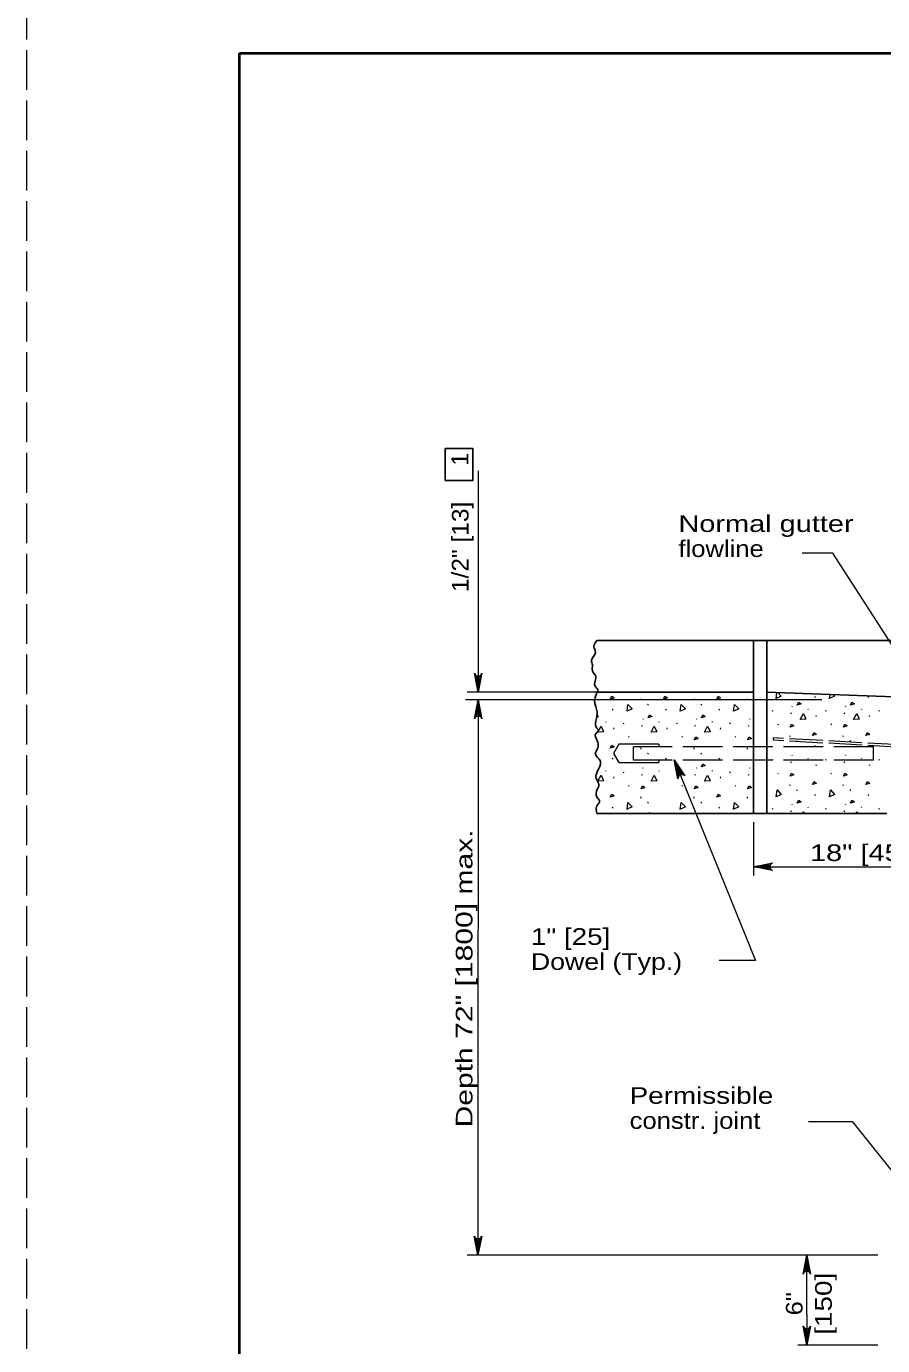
# Model space of a CAD drawing. Extents: x 1083.1 to 1117.1, y 719.4 to 763.4.
# Drawn here: x 1083.13 to 1091.16, y 728.74 to 741.1 of the extents above; entities that cross this region are included whole.
import ezdxf
from ezdxf.enums import TextEntityAlignment as Align

# ---------------------------------------------------------------- set-up
doc = ezdxf.new("R2010")
doc.units = 0
doc.header["$LTSCALE"] = 0.062
doc.linetypes.add('LONG_DASHED', pattern=[7.5, 6, -1.5])
doc.layers.add('1', color=7, linetype='Continuous', lineweight=13)

msp = doc.modelspace()

# ---------------------------------------------------------------- linework, layer by layer
at = {"layer": '1', "lineweight": 25}
for p, q in [((1085.12642, 740.85408), (1116.62642, 740.85408)), ((1089.9465, 735.34842), (1089.9465, 733.72892)), ((1088.47783, 734.86417), (1089.9465, 734.86417)), ((1090.0715, 734.86417), (1092.04017, 734.79308)), ((1089.9465, 733.72892), (1090.0715, 733.72892))]:
    msp.add_line(p, q, dxfattribs=at)
at = {"layer": '1'}
for p, q in [((1087.36392, 736.94033), (1087.36392, 734.86408)), ((1087.3415, 735.02442), (1087.36392, 734.86408)), ((1087.35258, 735.01892), (1087.36392, 734.86408)), ((1087.38875, 735.02625), (1087.36392, 734.86408)), ((1087.37833, 735.02017), (1087.36392, 734.86408)), ((1087.36392, 735.01733), (1087.36392, 734.86408)), ((1090.5885, 734.79308), (1087.2445, 734.79308)), ((1088.47783, 734.86417), (1087.26208, 734.86417)), ((1087.33917, 734.63075), (1087.36392, 734.79292)), ((1087.34958, 734.63683), (1087.36392, 734.79292)), ((1087.36392, 734.63967), (1087.36392, 734.79292)), ((1087.37525, 734.638), (1087.36392, 734.79292)), ((1087.38642, 734.63258), (1087.36392, 734.79292)), ((1088.88692, 734.80117), (1088.88808, 734.79117)), ((1088.95617, 734.74225), (1088.96058, 734.75225)), ((1089.38683, 734.80117), (1089.388, 734.79117)), ((1089.45608, 734.74225), (1089.4605, 734.75225)), ((1089.88683, 734.80117), (1089.888, 734.79117)), ((1090.15817, 734.80342), (1090.16617, 734.86075)), ((1090.52308, 734.81483), (1090.52758, 734.82483)), ((1090.65817, 734.80342), (1090.66367, 734.84275)), ((1091.023, 734.81483), (1091.0275, 734.82483)), ((1088.62483, 734.69667), (1088.62933, 734.70667)), ((1089.12475, 734.69667), (1089.12933, 734.70667)), ((1089.62475, 734.69667), (1089.62925, 734.70667)), ((1090.12417, 734.68608), (1090.12858, 734.69608)), ((1090.29733, 734.66292), (1090.30175, 734.67292)), ((1090.30567, 734.73608), (1090.31017, 734.72942)), ((1090.45525, 734.70783), (1090.45967, 734.70117)), ((1090.53425, 734.63742), (1090.53867, 734.64742)), ((1090.62417, 734.68608), (1090.62858, 734.69608)), ((1090.79733, 734.66292), (1090.80175, 734.67292)), ((1090.80567, 734.73608), (1090.81017, 734.72942)), ((1090.95517, 734.70783), (1090.95958, 734.70117)), ((1091.03417, 734.63742), (1091.03858, 734.64742)), ((1091.12408, 734.68608), (1091.1285, 734.69608)), ((1088.557, 734.58967), (1088.56142, 734.583)), ((1088.636, 734.51933), (1088.64042, 734.52933)), ((1088.72592, 734.56792), (1088.73033, 734.57792)), ((1088.89908, 734.54475), (1088.9035, 734.55475)), ((1088.90742, 734.61792), (1088.91192, 734.61125)), ((1089.057, 734.58967), (1089.06142, 734.583)), ((1089.136, 734.51933), (1089.14033, 734.52933)), ((1089.22583, 734.56792), (1089.23025, 734.57792)), ((1089.399, 734.54475), (1089.40342, 734.55475)), ((1089.40733, 734.61792), (1089.41183, 734.61125)), ((1089.55692, 734.58967), (1089.56133, 734.583)), ((1089.63592, 734.51933), (1089.64033, 734.52933)), ((1089.72583, 734.56792), (1089.73025, 734.57792)), ((1089.899, 734.54475), (1089.90342, 734.55475)), ((1089.90733, 734.61792), (1089.91183, 734.61125)), ((1090.173, 734.56633), (1090.17742, 734.55967)), ((1090.673, 734.56633), (1090.67742, 734.55967)), ((1088.77475, 734.44825), (1088.77917, 734.44167)), ((1089.27467, 734.44825), (1089.27908, 734.44167)), ((1089.77467, 734.44825), (1089.77908, 734.44167)), ((1090.28517, 734.46), (1090.28633, 734.45)), ((1090.35442, 734.40108), (1090.35883, 734.41108)), ((1090.78517, 734.46), (1090.78633, 734.45)), ((1090.85442, 734.40108), (1090.85883, 734.41108)), ((1088.88692, 734.34183), (1088.88808, 734.33183)), ((1088.95617, 734.28292), (1088.96058, 734.29292)), ((1089.05867, 734.37725), (1089.05867, 734.35383)), ((1089.38683, 734.34183), (1089.388, 734.33183)), ((1089.45608, 734.28292), (1089.4605, 734.29292)), ((1089.88683, 734.34183), (1089.888, 734.33183)), ((1090.30567, 734.27675), (1090.31017, 734.27008)), ((1090.52308, 734.3555), (1090.52758, 734.3655)), ((1090.80567, 734.27675), (1090.81017, 734.27008)), ((1091.023, 734.3555), (1091.0275, 734.3655)), ((1088.62483, 734.23733), (1088.62933, 734.24733)), ((1088.90742, 734.15858), (1088.91192, 734.15192)), ((1089.05867, 734.22883), (1089.05867, 734.20542)), ((1089.12475, 734.23733), (1089.12933, 734.24733)), ((1089.261, 734.08767), (1089.20233, 734.22925)), ((1089.24875, 734.07958), (1089.20233, 734.22925)), ((1089.2415, 734.06992), (1089.20233, 734.22925)), ((1089.27208, 734.0905), (1089.20233, 734.22925)), ((1089.28442, 734.08975), (1089.20233, 734.22925)), ((1089.40733, 734.15858), (1089.41183, 734.15192)), ((1089.62475, 734.23733), (1089.62925, 734.24733)), ((1089.90733, 734.15858), (1089.91183, 734.15192)), ((1090.12417, 734.22675), (1090.12858, 734.23675)), ((1090.29733, 734.20358), (1090.30175, 734.21358)), ((1090.45525, 734.2485), (1090.45967, 734.24183)), ((1090.53425, 734.17808), (1090.53867, 734.18808)), ((1090.62417, 734.22675), (1090.62858, 734.23675)), ((1090.79733, 734.20358), (1090.80175, 734.21358)), ((1090.95517, 734.2485), (1090.95958, 734.24183)), ((1091.03417, 734.17808), (1091.03858, 734.18808)), ((1091.12408, 734.22675), (1091.1285, 734.23675)), ((1088.557, 734.13033), (1088.56142, 734.12367)), ((1088.636, 734.05992), (1088.64042, 734.06992)), ((1088.72592, 734.10867), (1088.73033, 734.11858)), ((1088.89908, 734.08542), (1088.9035, 734.09542)), ((1089.057, 734.13033), (1089.06142, 734.12367)), ((1089.399, 734.08542), (1089.40342, 734.09542)), ((1089.55692, 734.13033), (1089.56133, 734.12367)), ((1089.63592, 734.05992), (1089.64033, 734.06992)), ((1089.72583, 734.10867), (1089.73025, 734.11858)), ((1089.899, 734.08542), (1089.90342, 734.09542)), ((1090.173, 734.107), (1090.17742, 734.10033)), ((1090.673, 734.107), (1090.67742, 734.10033)), ((1088.77475, 733.98892), (1088.77917, 733.98233)), ((1089.27467, 733.98892), (1089.27908, 733.98233)), ((1089.77467, 733.98892), (1089.77908, 733.98233)), ((1090.28517, 734.00058), (1090.28633, 733.99067)), ((1090.35442, 733.94175), (1090.35883, 733.95175)), ((1090.52308, 733.89617), (1090.52758, 733.90617)), ((1090.78517, 734.00058), (1090.78633, 733.99067)), ((1090.85442, 733.94175), (1090.85883, 733.95175)), ((1091.023, 733.89617), (1091.0275, 733.90617)), ((1088.62483, 733.77808), (1088.62933, 733.78808)), ((1088.88692, 733.8825), (1088.88808, 733.8725)), ((1088.95617, 733.82358), (1088.96058, 733.83358)), ((1089.38683, 733.8825), (1089.388, 733.8725)), ((1089.45608, 733.82358), (1089.4605, 733.83358)), ((1089.62475, 733.77808), (1089.62925, 733.78808)), ((1089.88683, 733.8825), (1089.888, 733.8725)), ((1090.12417, 733.76742), (1090.12858, 733.77742)), ((1090.30567, 733.81742), (1090.31017, 733.81075)), ((1090.45525, 733.78917), (1090.45967, 733.7825)), ((1090.62417, 733.76742), (1090.62858, 733.77742)), ((1090.80567, 733.81742), (1090.81017, 733.81075)), ((1090.95517, 733.78917), (1090.95958, 733.7825)), ((1091.12408, 733.76742), (1091.1285, 733.77742)), ((1088.47775, 733.73017), (1088.47942, 733.72892)), ((1089.9465, 733.64558), (1089.9465, 733.14567)), ((1090.29733, 733.74425), (1090.30175, 733.75425)), ((1090.79733, 733.74425), (1090.80175, 733.75425)), ((1090.10683, 733.25142), (1089.9465, 733.229)), ((1090.10142, 733.24033), (1089.9465, 733.229)), ((1089.9465, 733.229), (1091.15692, 733.229)), ((1090.09975, 733.229), (1089.9465, 733.229)), ((1090.10258, 733.21458), (1089.9465, 733.229)), ((1090.10867, 733.20417), (1089.9465, 733.229)), ((1091.15692, 733.229), (1092.1965, 733.229)), ((1087.33942, 729.74917), (1087.36183, 729.58892)), ((1087.3505, 729.74375), (1087.36183, 729.58892)), ((1087.38658, 729.75108), (1087.36183, 729.58892)), ((1087.37625, 729.74492), (1087.36183, 729.58892)), ((1087.36183, 729.74208), (1087.36183, 729.58892)), ((1091.11308, 729.58892), (1087.26208, 729.58892)), ((1090.42167, 729.42667), (1090.4465, 729.58892)), ((1090.43208, 729.43283), (1090.4465, 729.58892)), ((1090.4465, 729.03167), (1090.4465, 729.58892)), ((1090.4465, 729.43567), (1090.4465, 729.58892)), ((1090.45783, 729.434), (1090.4465, 729.58892)), ((1090.46892, 729.42858), (1090.4465, 729.58892)), ((1090.4465, 729.03167), (1090.4465, 728.74517)), ((1090.42408, 728.90558), (1090.4465, 728.74525)), ((1090.43517, 728.90017), (1090.4465, 728.74525)), ((1090.47125, 728.90742), (1090.4465, 728.74525)), ((1090.46092, 728.90133), (1090.4465, 728.74525)), ((1090.4465, 728.8985), (1090.4465, 728.74525)), ((1091.11308, 728.74525), (1090.36317, 728.74525))]:
    msp.add_line(p, q, dxfattribs=at)
at = {"layer": '1', "linetype": 'LONG_DASHED'}
for p, q in [((1090.13317, 734.414), (1090.1345, 734.43683)), ((1090.2295, 734.40867), (1090.13317, 734.414)), ((1090.22808, 734.43158), (1090.1345, 734.43683)), ((1090.59583, 734.41117), (1090.28375, 734.4285)), ((1090.59725, 734.38825), (1090.28525, 734.40558)), ((1090.9635, 734.39075), (1090.65158, 734.40808)), ((1090.96492, 734.36783), (1090.65308, 734.38517)), ((1091.33125, 734.37033), (1091.01917, 734.38767)), ((1088.82158, 734.22883), (1088.82158, 734.35383)), ((1091.33275, 734.34742), (1091.02067, 734.36475)), ((1091.07142, 734.22883), (1088.82158, 734.22883))]:
    msp.add_line(p, q, dxfattribs=at)
msp.add_lwpolyline([(1083.12642, 719.35408), (1117.12642, 719.35408), (1117.12642, 741.35408), (1083.12642, 741.35408)], close=True, dxfattribs=at)
at = {"layer": '1', "lineweight": 25}
for points in [[(1116.62642, 719.85408), (1085.12642, 719.85408), (1085.12642, 740.85408)], [(1088.47783, 735.34842), (1089.9465, 735.34842), (1090.0715, 735.34842)], [(1091.19642, 733.72892), (1090.0715, 733.72892), (1090.0715, 735.34842)], [(1090.0715, 735.34842), (1091.29683, 735.34842), (1093.0845, 735.34842), (1094.87617, 735.34842), (1097.69617, 735.34842)], [(1089.9465, 733.72892), (1088.99875, 733.72892), (1088.47783, 733.72892)], [(1088.96883, 733.72892), (1088.97167, 733.73475), (1088.97942, 733.72892)]]:
    msp.add_lwpolyline(points, dxfattribs=at)
at = {"layer": '1', "lineweight": 40}
msp.add_lwpolyline([(1085.12642, 740.85408), (1116.62642, 740.85408), (1116.62642, 719.85408), (1085.12642, 719.85408)], close=True, dxfattribs=at)
msp.add_lwpolyline([(1085.12642, 740.85408), (1116.62642, 740.85408), (1116.62642, 719.85408), (1085.12642, 719.85408)], close=True, dxfattribs=at)
at = {"layer": '1', "lineweight": 25}
msp.add_lwpolyline([(1087.05342, 736.84933), (1087.31508, 736.84933), (1087.31508, 737.14817), (1087.05342, 737.14817)], close=True, dxfattribs=at)
at = {"layer": '1'}
for points in [[(1091.53008, 734.86417), (1090.6915, 736.16683), (1090.40142, 736.16683)], [(1087.39933, 735.04117), (1087.36392, 734.86408), (1087.3285, 735.04117)], [(1087.3285, 734.61583), (1087.36392, 734.79292), (1087.39933, 734.61583)], [(1087.36392, 734.79292), (1087.36217, 730.49425), (1087.36183, 729.58892)], [(1090.17317, 734.8605), (1090.20675, 734.82575), (1090.15917, 734.80375)], [(1090.69125, 734.84175), (1090.70675, 734.82575), (1090.65917, 734.80375)], [(1088.47658, 734.64975), (1088.49392, 734.63675), (1088.47475, 734.63075)], [(1088.75992, 734.68525), (1088.76875, 734.74867), (1088.8085, 734.70758), (1088.76092, 734.68558)], [(1089.25983, 734.68525), (1089.26867, 734.74867), (1089.30842, 734.70758), (1089.26083, 734.68558)], [(1089.75983, 734.68525), (1089.76867, 734.74867), (1089.80842, 734.70758), (1089.76083, 734.68558)], [(1090.38433, 734.60742), (1090.41433, 734.664), (1090.43767, 734.61192), (1090.3855, 734.60742)], [(1090.88433, 734.60742), (1090.91425, 734.664), (1090.93767, 734.61192), (1090.8855, 734.60742)], [(1088.48608, 734.48933), (1088.51608, 734.54592), (1088.53942, 734.49383), (1088.48725, 734.48933)], [(1088.98608, 734.48933), (1089.01608, 734.54592), (1089.03942, 734.49383), (1088.98725, 734.48933)], [(1089.486, 734.48933), (1089.516, 734.54592), (1089.53933, 734.49383), (1089.48717, 734.48933)], [(1089.05867, 734.37725), (1088.68367, 734.37725), (1088.63408, 734.29133), (1088.68367, 734.20542), (1089.05867, 734.20542)], [(1089.23742, 734.05208), (1089.20233, 734.22925), (1089.30283, 734.07925)], [(1089.20233, 734.22925), (1089.96633, 732.34867), (1089.6245, 732.34867)], [(1088.48608, 734.02992), (1088.51608, 734.08658), (1088.53942, 734.03442), (1088.48725, 734.02992)], [(1088.98608, 734.02992), (1089.01608, 734.08658), (1089.03942, 734.03442), (1088.98725, 734.02992)], [(1089.486, 734.02992), (1089.516, 734.08658), (1089.53933, 734.03442), (1089.48717, 734.02992)], [(1090.15817, 733.88475), (1090.167, 733.94817), (1090.20675, 733.90708), (1090.15917, 733.88508)], [(1090.65817, 733.88475), (1090.667, 733.94817), (1090.70675, 733.90708), (1090.65917, 733.88508)], [(1088.75992, 733.76658), (1088.76875, 733.83), (1088.8085, 733.78892), (1088.76092, 733.76692)], [(1089.25983, 733.76658), (1089.26867, 733.83), (1089.30842, 733.78892), (1089.26083, 733.76692)], [(1089.75983, 733.76658), (1089.76867, 733.83), (1089.80842, 733.78892), (1089.76083, 733.76692)], [(1089.46875, 733.72892), (1089.47158, 733.73475), (1089.47933, 733.72892)], [(1090.40558, 733.72892), (1090.41433, 733.74542), (1090.42175, 733.72892)], [(1090.90558, 733.72892), (1090.91425, 733.74542), (1090.92175, 733.72892)], [(1090.12358, 733.19358), (1089.9465, 733.229), (1090.12358, 733.26442)], [(1091.81125, 729.6685), (1090.87792, 730.83792), (1090.46358, 730.83792)], [(1087.39725, 729.76592), (1087.36183, 729.58892), (1087.32642, 729.76592)], [(1090.41108, 729.41183), (1090.4465, 729.58892), (1090.48192, 729.41183)], [(1090.48192, 728.92233), (1090.4465, 728.74525), (1090.41108, 728.92233)]]:
    msp.add_lwpolyline(points, dxfattribs=at)
for points in [[(1088.60292, 734.79942), (1088.61625, 734.82717), (1088.63842, 734.8105)], [(1089.10292, 734.79942), (1089.11625, 734.82717), (1089.13833, 734.8105)], [(1089.60283, 734.79942), (1089.61617, 734.82717), (1089.63833, 734.8105)], [(1090.35658, 734.74383), (1090.36992, 734.77158), (1090.39217, 734.75492)], [(1090.85658, 734.74383), (1090.86992, 734.77158), (1090.89217, 734.75492)], [(1088.95833, 734.62567), (1088.97167, 734.65342), (1088.99392, 734.63675)], [(1089.45825, 734.62567), (1089.47158, 734.65342), (1089.49383, 734.63675)], [(1090.2895, 734.5375), (1090.30283, 734.56525), (1090.32508, 734.54858)], [(1090.7895, 734.5375), (1090.80283, 734.56525), (1090.82508, 734.54858)], [(1089.39117, 734.41942), (1089.4045, 734.44717), (1089.42675, 734.4305)], [(1089.89117, 734.41942), (1089.9045, 734.44717), (1089.92675, 734.4305)], [(1090.50117, 734.45825), (1090.5145, 734.486), (1090.53667, 734.46933)], [(1091.00108, 734.45825), (1091.01442, 734.486), (1091.03658, 734.46933)], [(1088.60292, 734.34008), (1088.61625, 734.36783), (1088.63842, 734.35117)], [(1089.45825, 734.16633), (1089.47158, 734.19408), (1089.49383, 734.17742)], [(1090.2895, 734.07817), (1090.30283, 734.10592), (1090.32508, 734.08925)], [(1090.50117, 733.99883), (1090.5145, 734.02658), (1090.53667, 734.00992)], [(1090.7895, 734.07817), (1090.80283, 734.10592), (1090.82508, 734.08925)], [(1091.00108, 733.99883), (1091.01442, 734.02658), (1091.03658, 734.00992)], [(1088.60292, 733.88075), (1088.61625, 733.9085), (1088.63842, 733.89183)], [(1088.89125, 733.96008), (1088.90458, 733.98783), (1088.92683, 733.97117)], [(1089.39117, 733.96008), (1089.4045, 733.98783), (1089.42675, 733.97117)], [(1089.60283, 733.88075), (1089.61617, 733.9085), (1089.63833, 733.89183)], [(1089.89117, 733.96008), (1089.9045, 733.98783), (1089.92675, 733.97117)], [(1090.35658, 733.82517), (1090.36992, 733.85292), (1090.39217, 733.83625)], [(1090.85658, 733.82517), (1090.86992, 733.85292), (1090.89217, 733.83625)]]:
    msp.add_lwpolyline(points, close=True, dxfattribs=at)
at = {"layer": '1', "linetype": 'LONG_DASHED'}
msp.add_lwpolyline([(1091.07142, 734.22883), (1091.07142, 734.35383), (1088.82158, 734.35383)], dxfattribs=at)
at = {"layer": '1'}
for centre, start, end in [((1087.36391, 735.05545), 202.08782, 337.91395), ((1087.36399, 734.60154), 22.08782, 157.91395), ((1089.27563, 734.05247), 44.58395, 180.41008), ((1090.13788, 733.22903), 112.08782, 247.91395), ((1087.36177, 729.78026), 202.08782, 337.91395), ((1090.44652, 729.39751), 22.08782, 157.91395), ((1090.44644, 728.93663), 202.08782, 337.91395)]:
    msp.add_arc(centre, 0.03822, start, end, dxfattribs=at)
at = {"layer": '1', "lineweight": 25}
for points in [[(1088.47783, 734.86417), (1088.48633, 734.88942), (1088.46683, 734.91092), (1088.457, 734.95192), (1088.46875, 735.00667), (1088.43558, 735.06525), (1088.43558, 735.11992), (1088.42775, 735.16292), (1088.46292, 735.23525), (1088.44925, 735.29383), (1088.47783, 735.34842)], [(1088.47783, 734.86417), (1088.46683, 734.83217), (1088.457, 734.76575), (1088.46683, 734.73058), (1088.4785, 734.68167), (1088.46875, 734.59375), (1088.47658, 734.52742), (1088.49408, 734.50783), (1088.48242, 734.49025), (1088.46092, 734.46292), (1088.48042, 734.41208), (1088.48633, 734.34367), (1088.46292, 734.28308), (1088.50775, 734.2245), (1088.47067, 734.09158), (1088.47267, 734.04858), (1088.49608, 733.99975), (1088.47458, 733.93725), (1088.48633, 733.86883), (1088.48825, 733.86692), (1088.50192, 733.8415), (1088.48825, 733.81608), (1088.47267, 733.79067), (1088.47783, 733.72892)]]:
    msp.add_spline(points, degree=3, dxfattribs=at)

# ---------------------------------------------------------------- texts
at = {"layer": '1'}
msp.add_text('1', height=0.16, rotation=90, dxfattribs=at).set_placement((1087.27258, 736.98808))
for s, width, p in [('1/2" [13]', 1.1, (1087.2735, 736.22621)), ('[150]', 1.25, (1090.68042, 729.13317)), ('6"', 1.15, (1090.40633, 729.13317))]:
    msp.add_text(s, height=0.156, rotation=90, dxfattribs=dict(at, width=width)).set_placement(p, align=Align.CENTER)
for s, width, p in [('Normal gutter', 1.3, (1089.24233, 736.36608)), ('flowline', 1.15, (1089.24233, 736.13142)), ('1" [25]', 1.25, (1087.85842, 732.49642)), ('Dowel (Typ.)', 1.2, (1087.85842, 732.26175)), ('Permissible', 1.25, (1088.78475, 731.00667)), ('constr. joint', 1.15, (1088.78475, 730.772))]:
    msp.add_text(s, height=0.156, dxfattribs=dict(at, width=width)).set_placement(p)
at = {"layer": '1', "width": 1.35}
msp.add_text('Depth 72" [1800] max.', height=0.156, rotation=90, dxfattribs=at).set_placement((1087.31025, 730.7855))
at = {"layer": '1', "width": 1.3}
msp.add_text('18" [450]', height=0.156, dxfattribs=at).set_placement((1091.01463, 733.28192), align=Align.CENTER)

doc.saveas('drawing.dxf')
